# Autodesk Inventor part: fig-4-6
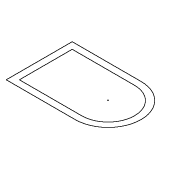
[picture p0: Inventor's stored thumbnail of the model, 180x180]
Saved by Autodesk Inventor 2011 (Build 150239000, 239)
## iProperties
Created: 2005-02
Part Number: fig-4-6
Document SubType Name: Modeling
Designer: CADCIM
Manufacturer: Standard
Standards Organization: Custom
Density: 1 g/cm^3
Author: CADCIM
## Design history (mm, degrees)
sketch "Sketch1"
  geometry: L1 (12.963, 23.563)-(-25.99, 23.563); L2 (-25.99, 23.563)-(-25.99, -13.729); L3 (-25.99, -13.729)-(12.963, -13.729); L4 (-22.275, 19.848)-(12.963, 19.848); L5 (12.963, -10.014)-(-22.275, -10.014); L6 (-22.275, -10.014)-(-22.275, 19.848); A1 r 18.646 centre (12.963, 4.917) between (12.963, -13.729) and (12.963, 23.563); A2 r 14.931 centre (12.963, 4.917) between (12.963, -10.014) and (12.963, 19.848)
  constraints: 12 end point, 4 point on circle, 2 centre point, 2 parallel, 2 perpendicular, 2 tangent, 1 horizontal, 4 other
